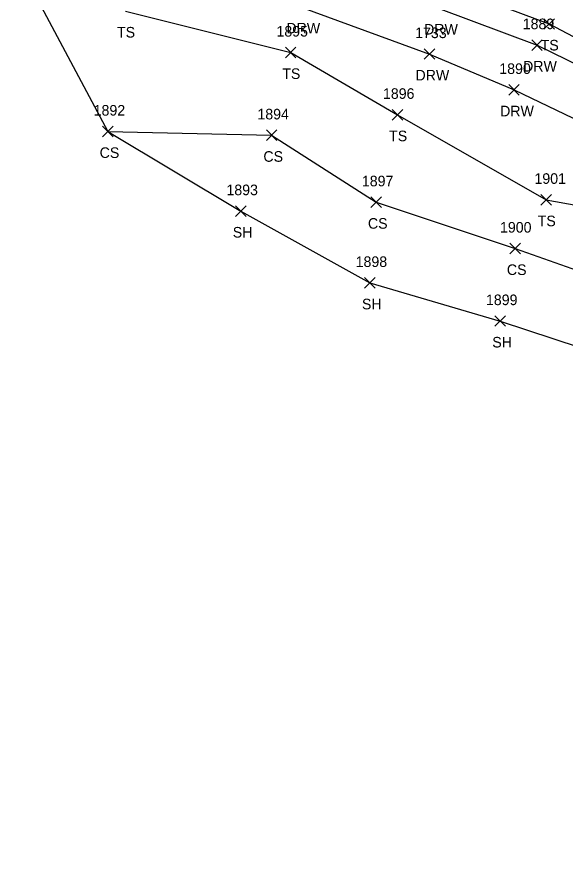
# Model space of a CAD drawing. Extents: x 1512665 to 1513714, y 110636 to 112816.
# Drawn here: x 1512677.7 to 1512781.5, y 110708.3 to 110869.1 of the extents above; entities that cross this region are included whole.
import ezdxf

# ---------------------------------------------------------------- set-up
doc = ezdxf.new("R2010")
doc.units = 0
for name, color, linetype in [('L_A', 7, 'Continuous'), ('L_I', 7, 'Continuous'), ('L_TIC', 7, 'Continuous'), ('LELB', 7, 'Continuous'), ('LSOGP', 7, 'Continuous'), ('R_A', 7, 'Continuous'), ('R_I', 7, 'Continuous'), ('R_TIC', 7, 'Continuous'), ('RDW', 7, 'Continuous')]:
    doc.layers.add(name, color=color, linetype=linetype)

msp = doc.modelspace()

# ---------------------------------------------------------------- linework, layer by layer
at = {"layer": 'L_TIC'}
for points in [[(1512777.26, 110866.83), (1512779.26, 110868.83)], [(1512779.26, 110866.83), (1512777.26, 110868.83)], [(1512728.45, 110861.45), (1512730.45, 110863.45)], [(1512730.45, 110861.45), (1512728.45, 110863.45)], [(1512748.63, 110849.69), (1512750.63, 110851.69)], [(1512750.63, 110849.69), (1512748.63, 110851.69)], [(1512693.92, 110846.53), (1512695.92, 110848.53)], [(1512695.92, 110846.53), (1512693.92, 110848.53)], [(1512724.85, 110845.81), (1512726.85, 110847.81)], [(1512726.85, 110845.81), (1512724.85, 110847.81)], [(1512744.6, 110833.17), (1512746.6, 110835.17)], [(1512746.6, 110833.17), (1512744.6, 110835.17)], [(1512776.7, 110833.64), (1512778.7, 110835.64)], [(1512778.7, 110833.64), (1512776.7, 110835.64)], [(1512719.01, 110831.5), (1512721.01, 110833.5)], [(1512721.01, 110831.5), (1512719.01, 110833.5)], [(1512770.85, 110824.43), (1512772.85, 110826.43)], [(1512772.85, 110824.43), (1512770.85, 110826.43)], [(1512743.42, 110817.94), (1512745.42, 110819.94)], [(1512745.42, 110817.94), (1512743.42, 110819.94)], [(1512768.04, 110810.74), (1512770.04, 110812.74)], [(1512770.04, 110810.74), (1512768.04, 110812.74)]]:
    msp.add_lwpolyline(points, dxfattribs=at)
at = {"layer": 'LELB'}
for points in [[(1512685.37, 110901.62), (1512704.39, 110894.87), (1512721.83, 110890.38), (1512736.95, 110883.29), (1512758.15, 110875.39), (1512778.26, 110867.83), (1512805.48, 110853.5), (1512829.24, 110847.86), (1512845.12, 110839.12), (1512864.92, 110836.03)], [(1512698.23, 110870.27), (1512729.45, 110862.45), (1512749.63, 110850.69), (1512777.7, 110834.64), (1512793.92, 110831.75), (1512815.55, 110826.53), (1512828.48, 110824.79), (1512839.13, 110821.43), (1512854.65, 110808.75), (1512864.61, 110809.77)], [(1512694.92, 110847.53), (1512725.85, 110846.81), (1512745.6, 110834.17), (1512771.85, 110825.43), (1512788.97, 110819.37), (1512803.93, 110806.13), (1512822.02, 110793.13), (1512819.62, 110775.5)]]:
    msp.add_lwpolyline(points, dxfattribs=at)
at = {"layer": 'LSOGP'}
msp.add_lwpolyline([(1512677.75, 110879.68), (1512694.93, 110847.53), (1512720.01, 110832.5), (1512744.42, 110818.94), (1512769.04, 110811.74), (1512784.16, 110806.73), (1512800.09, 110794.66), (1512819.62, 110775.51), (1512859.02, 110759.58), (1512880.03, 110750.81), (1512889.78, 110732.88), (1512896.82, 110720.33), (1512918.08, 110708.27)], dxfattribs=at)
at = {"layer": 'R_TIC'}
for points in [[(1512774.98, 110862.85), (1512776.98, 110864.85)], [(1512776.98, 110862.85), (1512774.98, 110864.85)], [(1512754.65, 110861.16), (1512756.65, 110863.16)], [(1512756.65, 110861.16), (1512754.65, 110863.16)], [(1512770.64, 110854.39), (1512772.64, 110856.39)], [(1512772.64, 110854.39), (1512770.64, 110856.39)]]:
    msp.add_lwpolyline(points, dxfattribs=at)
at = {"layer": 'RDW'}
for points in [[(1512678.69, 110893.12), (1512705.91, 110885.74), (1512730.91, 110879.48), (1512757.28, 110870.83), (1512775.98, 110863.85), (1512803.62, 110850.37), (1512827.04, 110842.82), (1512843.68, 110837.08), (1512859.31, 110829.49), (1512882.79, 110804.51), (1512900.46, 110800.08), (1512923.2, 110794.9)], [(1512677.75, 110879.68), (1512702.96, 110877.46), (1512731.26, 110871.04), (1512755.65, 110862.16), (1512771.64, 110855.39), (1512800.14, 110841.72), (1512826.02, 110832.15), (1512842.36, 110825.52), (1512852.9, 110823.11), (1512864.61, 110809.77), (1512882.31, 110793.7), (1512890.53, 110788.25), (1512897.02, 110786.49), (1512918.65, 110784.55)]]:
    msp.add_lwpolyline(points, dxfattribs=at)

# ---------------------------------------------------------------- texts
at = {"layer": 'L_A'}
for s, p in [('TS', (1512696.64, 110865.27)), ('TS', (1512776.67, 110862.83)), ('TS', (1512727.86, 110857.45)), ('TS', (1512748.04, 110845.69)), ('CS', (1512693.36, 110842.53)), ('CS', (1512724.29, 110841.81)), ('CS', (1512744.04, 110829.17)), ('TS', (1512776.11, 110829.64)), ('SH', (1512718.5, 110827.5)), ('CS', (1512770.29, 110820.43)), ('SH', (1512742.91, 110813.94)), ('SH', (1512767.53, 110806.74))]:
    msp.add_text(s, height=2, dxfattribs=at).set_placement(p)
at = {"layer": 'L_I'}
for s, p in [('1895', (1512726.76, 110865.45)), ('1896', (1512746.88, 110853.69)), ('1892', (1512692.23, 110850.53)), ('1894', (1512723.16, 110849.81)), ('1897', (1512742.9, 110837.17)), ('1901', (1512775.5, 110837.64)), ('1893', (1512717.31, 110835.5)), ('1900', (1512768.99, 110828.43)), ('1898', (1512741.72, 110821.94)), ('1899', (1512766.34, 110814.74))]:
    msp.add_text(s, height=2, dxfattribs=at).set_placement(p)
at = {"layer": 'R_A'}
for p in [(1512728.63, 110866.04), (1512754.65, 110865.83), (1512773.35, 110858.85), (1512753.02, 110857.16), (1512769.01, 110850.39)]:
    msp.add_text('DRW', height=2, dxfattribs=at).set_placement(p)
at = {"layer": 'R_I'}
for s, p in [('1889', (1512773.28, 110866.85)), ('1733', (1512752.96, 110865.16)), ('1890', (1512768.86, 110858.39))]:
    msp.add_text(s, height=2, dxfattribs=at).set_placement(p)

doc.saveas('drawing.dxf')
